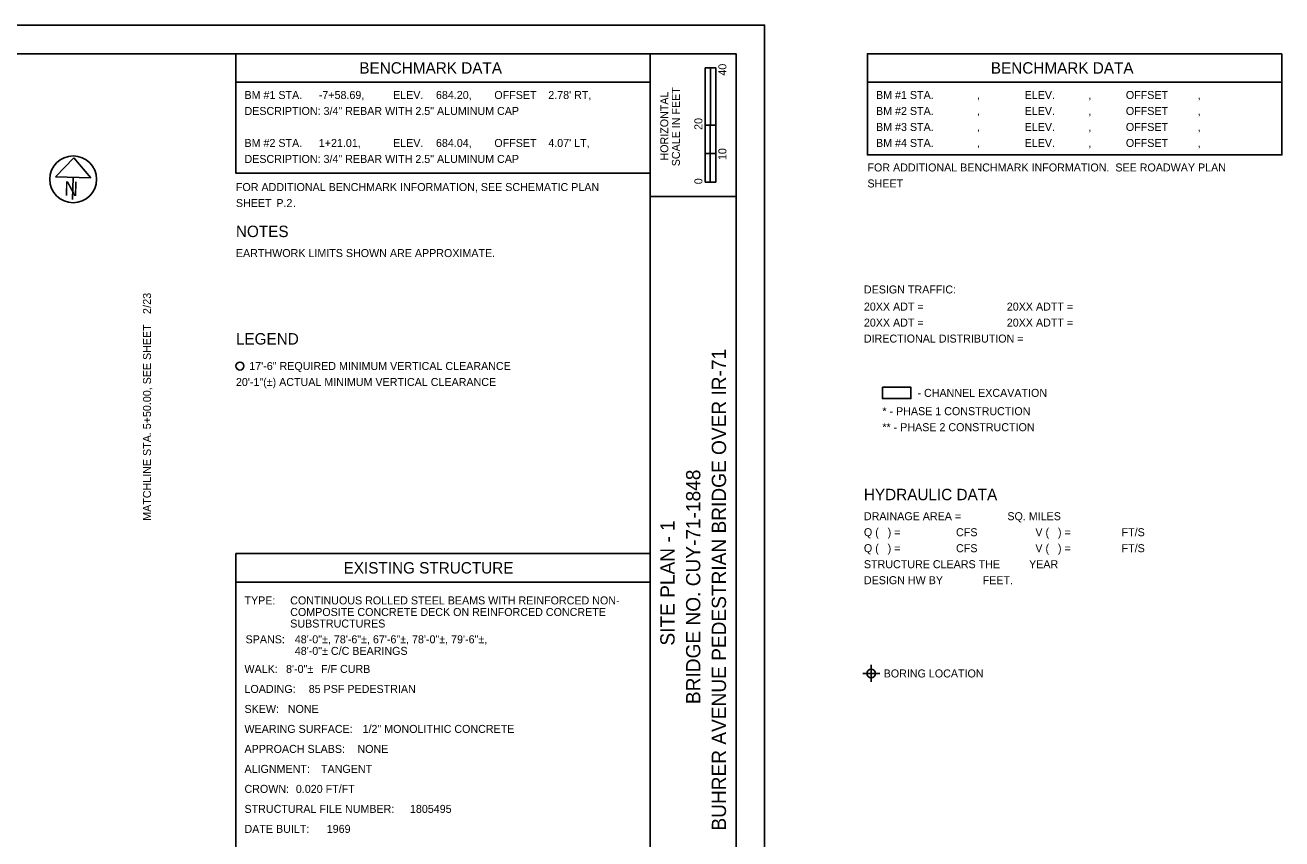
# Model space of a CAD drawing. Extents: x 58.8 to 101.8, y -10 to 13.1.
# Drawn here: x 79.85 to 101.84, y -1.11 to 13.14 of the extents above; entities that cross this region are included whole.
import ezdxf

# ---------------------------------------------------------------- set-up
doc = ezdxf.new("R2010")
doc.units = 0
for name, color, linetype in [('DT_X_Break_Line', 7, 'Continuous'), ('DT_X_Contour_Major', 7, 'Continuous'), ('DT_X_Contour_Minor', 7, 'Continuous'), ('DT_X_Island', 7, 'Continuous'), ('DT_X_Spot_Elev', 7, 'Continuous'), ('DT_X_Void', 7, 'Continuous')]:
    doc.layers.add(name, color=color, linetype=linetype)

msp = doc.modelspace()

# ---------------------------------------------------------------- linework, layer by layer
at = {"layer": 'DT_X_Break_Line'}
for p, q in [((94.653, 1.788), (94.503, 1.788)), ((94.653, 1.788), (94.578, 1.788)), ((94.653, 1.788), (94.653, 1.938)), ((94.653, 1.863), (94.653, 1.788)), ((94.653, 1.788), (94.653, 1.638)), ((94.653, 1.788), (94.803, 1.788)), ((94.653, 1.713), (94.653, 1.788)), ((94.653, 1.788), (94.728, 1.788))]:
    msp.add_line(p, q, dxfattribs=at)
msp.add_circle((94.653, 1.788), 0.075, dxfattribs=at)
for start, end in [(90, 180), (270, 360)]:
    msp.add_arc((94.653, 1.788), 0.075, start, end, dxfattribs=at)
at = {"layer": 'DT_X_Contour_Major'}
for p, q in [((91.744, 11.388), (91.744, 12.388)), ((91.744, 12.388), (91.837, 12.388)), ((91.744, 10.388), (91.744, 12.388)), ((91.931, 12.388), (91.744, 12.388)), ((91.837, 12.388), (91.838, 12.388)), ((91.838, 12.388), (91.838, 11.388)), ((91.931, 12.388), (91.931, 10.388)), ((83.537, 12.138), (90.787, 12.138)), ((94.586, 12.138), (101.836, 12.138)), ((91.838, 11.388), (91.744, 11.388)), ((91.931, 11.388), (91.837, 11.388)), ((91.837, 11.388), (91.837, 10.888)), ((91.931, 10.888), (91.931, 11.388)), ((91.837, 10.888), (91.744, 10.888)), ((91.744, 10.888), (91.744, 10.388)), ((91.837, 10.888), (91.931, 10.888)), ((91.837, 10.388), (91.837, 10.888)), ((91.931, 10.388), (91.744, 10.388)), ((91.744, 10.388), (91.837, 10.388)), ((90.787, 3.386), (83.537, 3.386))]:
    msp.add_line(p, q, dxfattribs=at)
for points in [[(90.787, 12.638), (83.537, 12.638), (83.537, 10.544), (90.787, 10.544)], [(101.836, 12.638), (94.586, 12.638), (94.586, 10.865), (101.836, 10.865)], [(94.847, 6.799), (95.347, 6.799), (95.347, 6.599), (94.847, 6.599)], [(83.537, 3.886), (90.787, 3.886), (90.787, -1.729), (83.537, -1.729)]]:
    msp.add_lwpolyline(points, close=True, dxfattribs=at)
msp.add_circle((83.607, 7.169), 0.07, dxfattribs=at)
at = {"layer": 'DT_X_Contour_Minor'}
msp.add_lwpolyline([(58.787, -8.862), (92.787, -8.862), (92.787, 13.138), (58.787, 13.138)], close=True, dxfattribs=at)
at = {"layer": 'DT_X_Island'}
for p, q in [((80.701, 10.813), (80.383, 10.481)), ((80.998, 10.463), (80.701, 10.813)), ((80.383, 10.481), (80.998, 10.463)), ((80.691, 10.472), (80.679, 10.085))]:
    msp.add_line(p, q, dxfattribs=at)
msp.add_circle((80.69, 10.439), 0.41, dxfattribs=at)
at = {"layer": 'DT_X_Spot_Elev'}
for p, q in [((90.787, -8.362), (90.787, 12.638)), ((90.787, 10.138), (92.287, 10.138))]:
    msp.add_line(p, q, dxfattribs=at)
msp.add_lwpolyline([(60.287, 12.638), (92.287, 12.638), (92.287, -8.362), (60.287, -8.362)], close=True, dxfattribs=at)
at = {"layer": 'DT_X_Void'}
msp.add_circle((80.69, 10.439), 0.41, dxfattribs=at)

# ---------------------------------------------------------------- texts
at = {"layer": 'DT_X_Contour_Major'}
for s, height, p in [('BENCHMARK DATA', 0.2, (85.696, 12.288)), ('BENCHMARK DATA', 0.2, (96.745, 12.288)), ('BM #1 STA.', 0.14, (83.687, 11.845)), ('-7+58.69,', 0.14, (84.987, 11.845)), ('ELEV.', 0.14, (86.287, 11.845)), ('684.20,', 0.14, (87.037, 11.845)), ('OFFSET', 0.14, (88.058, 11.845)), ("2.78' RT,", 0.14, (89.002, 11.845)), ('BM #1 STA.', 0.14, (94.736, 11.845)), ('ELEV.', 0.14, (97.336, 11.845)), ('OFFSET', 0.14, (99.107, 11.845)), ('DESCRIPTION: 3/4" REBAR WITH 2.5" ALUMINUM CAP', 0.14, (83.687, 11.565)), ('BM #2 STA.', 0.14, (94.736, 11.565)), ('         ,', 0.14, (96.036, 11.845)), ('ELEV.', 0.14, (97.336, 11.565)), ('       ,', 0.14, (98.086, 11.845)), ('OFFSET', 0.14, (99.107, 11.565)), ('      ,', 0.14, (100.052, 11.845)), ('         ,', 0.14, (96.036, 11.565)), ('       ,', 0.14, (98.086, 11.565)), ('      ,', 0.14, (100.052, 11.565)), ('BM #3 STA.', 0.14, (94.736, 11.285)), ('         ,', 0.14, (96.036, 11.285)), ('ELEV.', 0.14, (97.336, 11.285)), ('       ,', 0.14, (98.086, 11.285)), ('OFFSET', 0.14, (99.107, 11.285)), ('      ,', 0.14, (100.052, 11.285)), ('BM #2 STA.', 0.14, (83.687, 11.005)), ('1+21.01,', 0.14, (84.987, 11.005)), ('ELEV.', 0.14, (86.287, 11.005)), ('684.04,', 0.14, (87.037, 11.005)), ('OFFSET', 0.14, (88.058, 11.005)), ("4.07' LT,", 0.14, (89.002, 11.005)), ('BM #4 STA.', 0.14, (94.736, 11.005)), ('         ,', 0.14, (96.036, 11.005)), ('ELEV.', 0.14, (97.336, 11.005)), ('       ,', 0.14, (98.086, 11.005)), ('OFFSET', 0.14, (99.107, 11.005)), ('      ,', 0.14, (100.052, 11.005)), ('DESCRIPTION: 3/4" REBAR WITH 2.5" ALUMINUM CAP', 0.14, (83.687, 10.725)), ('FOR ADDITIONAL BENCHMARK INFORMATION.  SEE ROADWAY PLAN', 0.14, (94.586, 10.576)), ('FOR ADDITIONAL BENCHMARK INFORMATION, SEE SCHEMATIC PLAN', 0.14, (83.537, 10.233)), ('SHEET      ', 0.14, (94.586, 10.296)), ('SHEET ', 0.14, (83.537, 9.953)), ('P.2', 0.14, (84.244, 9.953)), ('.', 0.14, (84.537, 9.953)), ('NOTES', 0.2, (83.537, 9.427)), ('EARTHWORK LIMITS SHOWN ARE APPROXIMATE.  ', 0.14, (83.537, 9.077)), ('DESIGN TRAFFIC:', 0.14, (94.524, 8.44)), ('20XX ADT =', 0.14, (94.524, 8.14)), ('20XX ADTT =', 0.14, (97.024, 8.14)), ('20XX ADT =', 0.14, (94.524, 7.86)), ('20XX ADTT =', 0.14, (97.024, 7.86)), ('LEGEND', 0.2, (83.537, 7.545)), ('DIRECTIONAL DISTRIBUTION =', 0.14, (94.524, 7.58)), ('- CHANNEL EXCAVATION', 0.14, (95.461, 6.629)), ('* - PHASE 1 CONSTRUCTION', 0.14, (94.847, 6.309)), ('** - PHASE 2 CONSTRUCTION', 0.14, (94.847, 6.029)), ('HYDRAULIC DATA', 0.2, (94.524, 4.82)), ('DRAINAGE AREA =', 0.14, (94.524, 4.47)), ('SQ. MILES', 0.14, (97.034, 4.47)), ('Q (   ) =', 0.14, (94.524, 4.19)), ('      CFS', 0.14, (95.824, 4.19)), ('V (   ) =', 0.14, (97.524, 4.19)), ('    FT/S', 0.14, (98.824, 4.19)), ('Q (   ) =', 0.14, (94.524, 3.91)), ('      CFS', 0.14, (95.824, 3.91)), ('V (   ) =', 0.14, (97.524, 3.91)), ('    FT/S', 0.14, (98.824, 3.91)), ('EXISTING STRUCTURE', 0.2, (85.421, 3.536)), ('STRUCTURE CLEARS THE', 0.14, (94.524, 3.63)), ('YEAR', 0.14, (97.414, 3.63)), ('DESIGN HW BY', 0.14, (94.524, 3.35)), ('FEET.', 0.14, (96.601, 3.35)), ('TYPE:', 0.14, (83.687, 2.996)), ('CONTINUOUS ROLLED STEEL BEAMS WITH REINFORCED NON-', 0.14, (84.487, 2.996)), ('COMPOSITE CONCRETE DECK ON REINFORCED CONCRETE ', 0.14, (84.487, 2.793)), ('SUBSTRUCTURES', 0.14, (84.487, 2.591)), ('SPANS:', 0.14, (83.706, 2.315)), ('48\'-0"±, 78\'-6"±, 67\'-6"±, 78\'-0"±, 79\'-6"±, ', 0.14, (84.567, 2.315)), ('48\'-0"± C/C BEARINGS', 0.14, (84.567, 2.112)), ('WALK:', 0.14, (83.687, 1.796)), ('8\'-0"±', 0.14, (84.414, 1.796)), ('F/F CURB', 0.14, (85.026, 1.796)), ('BORING LOCATION', 0.14, (94.87, 1.717)), ('LOADING:', 0.14, (83.687, 1.446)), ('85 PSF PEDESTRIAN', 0.14, (84.811, 1.446)), ('SKEW:', 0.14, (83.687, 1.096)), ('NONE', 0.14, (84.445, 1.096)), ('WEARING SURFACE:', 0.14, (83.687, 0.746)), ('1/2" MONOLITHIC CONCRETE', 0.14, (85.753, 0.746)), ('APPROACH SLABS:', 0.14, (83.687, 0.396)), ('NONE', 0.14, (85.663, 0.396)), ('ALIGNMENT:', 0.14, (83.687, 0.046)), ('TANGENT', 0.14, (85.026, 0.046)), ('CROWN:', 0.14, (83.687, -0.304)), ('0.020 FT/FT', 0.14, (84.586, -0.304)), ('STRUCTURAL FILE NUMBER:', 0.14, (83.687, -0.654)), ('1805495', 0.14, (86.582, -0.654)), ('DATE BUILT:', 0.14, (83.687, -1.004)), ('1969', 0.14, (85.126, -1.004))]:
    msp.add_text(s, height=height, dxfattribs=at).set_placement(p)
for s, height, rotation, p in [('40', 0.14, 90, (92.118, 12.254)), ('HORIZONTAL', 0.14, 90, (91.102, 10.768)), ('SCALE IN FEET', 0.14, 90, (91.305, 10.667)), ('20', 0.14, 90, (91.698, 11.304)), ('10', 0.14, 90, (92.118, 10.775)), ('0', 0.14, 90, (91.698, 10.352)), ('BUHRER AVENUE PEDESTRIAN BRIDGE OVER IR-71', 0.25, 90, (92.112, -0.964)), ('17\'-6" REQUIRED MINIMUM VERTICAL CLEARANCE', 0.14, 0, (83.771, 7.1)), ('20\'-1"(±) ACTUAL MINIMUM VERTICAL CLEARANCE', 0.14, 0, (83.537, 6.82)), ('BRIDGE NO. CUY-71-1848', 0.25, 90, (91.662, 1.251)), ('SITE PLAN - 1', 0.25, 90, (91.212, 2.275))]:
    msp.add_text(s, height=height, rotation=rotation, dxfattribs=at).set_placement(p)
at = {"layer": 'DT_X_Island'}
for s, height, rotation, p in [('N', 0.25, 358.2375, (80.53, 10.153)), ('23', 0.14, 90, (82.051, 8.242)), ('/', 0.14, 90, (82.051, 8.188)), ('2', 0.14, 90, (82.051, 8.079)), ('MATCHLINE STA. 5+50.00, SEE SHEET ', 0.14, 90, (82.051, 4.461))]:
    msp.add_text(s, height=height, rotation=rotation, dxfattribs=at).set_placement(p)

doc.saveas('drawing.dxf')
